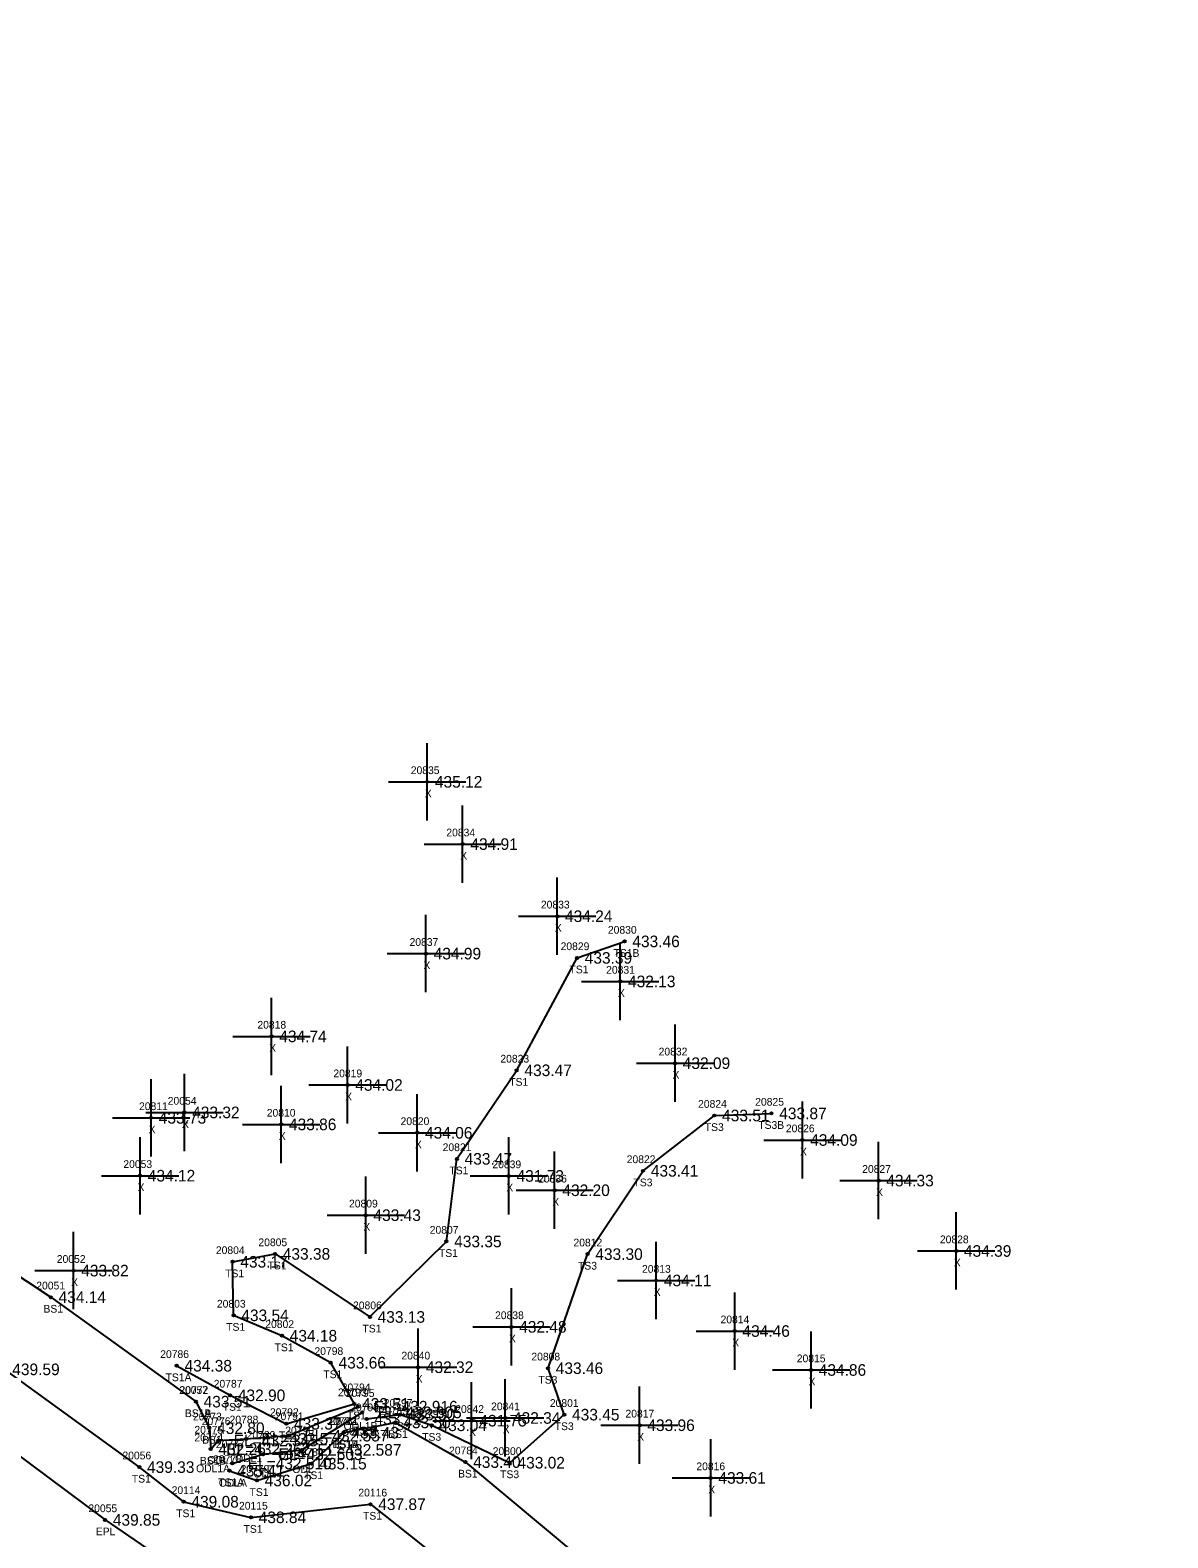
# Model space of a CAD drawing. Extents: x 1613836 to 1615109, y 777151 to 778248.
# Drawn here: x 1614182.4 to 1614329.5, y 777918.3 to 778113.4 of the extents above; entities that cross this region are included whole.
import ezdxf

# ---------------------------------------------------------------- set-up
doc = ezdxf.new("R2010")
doc.units = 0
for name, color, linetype in [('RD_DTM_BkLn2', 7, 'Continuous'), ('RD_DTM_BkLn_txCode', 7, 'Continuous'), ('RD_EX_H2O', 7, 'Continuous'), ('RD_EX_H2O_txCode', 7, 'Continuous'), ('RD_EX_Misc', 7, 'Continuous'), ('RD_EX_Misc_txCode', 7, 'Continuous'), ('RD_EX_Road', 7, 'Continuous'), ('RD_EX_Road_txCode', 7, 'Continuous'), ('RD_EX_TX_H2O_ELEV', 7, 'Continuous'), ('RD_EX_TX_Misc_ELEV', 7, 'Continuous'), ('RD_EX_TX_Road_ELEV', 7, 'Continuous'), ('RD_SMD_Locator', 7, 'Continuous')]:
    doc.layers.add(name, color=color, linetype=linetype)

msp = doc.modelspace()

# ---------------------------------------------------------------- linework, layer by layer
at = {"layer": 'RD_DTM_BkLn2'}
for points in [[(1613872.63, 778113.36), (1613919.46, 778094.34), (1613965.43, 778074.52), (1614011.49, 778053.16), (1614057.96, 778027.92), (1614098.58, 778001.66), (1614142.66, 777977.46), (1614185.05, 777949.4), (1614203.81, 777935.88)], [(1613870.65, 778107.91), (1613917.36, 778089.81), (1613963.47, 778068.53), (1614008.76, 778046.32), (1614052.42, 778023.01), (1614094.96, 777996.37), (1614137.71, 777969), (1614179.06, 777940.06), (1614196.49, 777927.41), (1614202.23, 777922.93), (1614210.94, 777920.91), (1614226.4, 777922.61), (1614267.62, 777889.85), (1614307.16, 777859.76), (1614381.32, 777790.21), (1614451.43, 777721.4), (1614453.49, 777722.08), (1614455.33, 777720.48), (1614437.07, 777696.16)], [(1614201.34, 777940.53), (1614208.24, 777936.7), (1614215.51, 777933.02), (1614224.31, 777935.59), (1614221.26, 777940.92), (1614214.95, 777944.41), (1614208.69, 777947.05), (1614208.56, 777953.98), (1614214.05, 777955), (1614226.32, 777946.84), (1614236.22, 777956.61), (1614237.57, 777967.3), (1614245.31, 777978.76), (1614253.11, 777993.31), (1614259.27, 777995.44)], [(1614225.91, 777933.64), (1614230.23, 777934.21), (1614234.33, 777932.82), (1614244.41, 777927.98), (1614251.47, 777934.2), (1614249.36, 777940.21), (1614254.48, 777954.97), (1614261.66, 777965.75), (1614270.88, 777972.91), (1614278.27, 777973.18)], [(1614203.81, 777935.88), (1614205.56, 777932.45), (1614205.73, 777929.74)], [(1614208.15, 777926.94), (1614211.71, 777925.68), (1614218.77, 777927.86), (1614222.94, 777931.87)], [(1614222.94, 777931.87), (1614229.64, 777933.19), (1614238.68, 777928.06), (1614263.24, 777907.54)]]:
    msp.add_lwpolyline(points, dxfattribs=at)
at = {"layer": 'RD_EX_H2O'}
for points in [[(1614205.73, 777929.74), (1614206.71, 777930.85), (1614210.29, 777931.06), (1614215.85, 777931.48), (1614224.8, 777935.23)], [(1614208.51, 777927.88), (1614212.5, 777929.07), (1614217.53, 777929.64), (1614225.32, 777934.49)]]:
    msp.add_lwpolyline(points, dxfattribs=at)
at = {"layer": 'RD_EX_Misc'}
for p, q in [((1614233.73, 778011.09), (1614233.73, 778021.09)), ((1614228.73, 778016.09), (1614238.73, 778016.09)), ((1614238.32, 778003.03), (1614238.32, 778013.03)), ((1614233.32, 778008.03), (1614243.32, 778008.03)), ((1614250.56, 777993.7), (1614250.56, 778003.7)), ((1614233.57, 777988.86), (1614233.57, 777998.86)), ((1614245.56, 777998.7), (1614255.56, 777998.7)), ((1614258.71, 777985.26), (1614258.71, 777995.26)), ((1614228.57, 777993.86), (1614238.57, 777993.86)), ((1614253.71, 777990.26), (1614263.71, 777990.26)), ((1614213.6, 777978.15), (1614213.6, 777988.15)), ((1614265.79, 777974.68), (1614265.79, 777984.68)), ((1614208.6, 777983.15), (1614218.6, 777983.15)), ((1614223.43, 777971.86), (1614223.43, 777981.86)), ((1614260.79, 777979.68), (1614270.79, 777979.68)), ((1614198.01, 777967.61), (1614198.01, 777977.61)), ((1614202.33, 777968.31), (1614202.33, 777978.31)), ((1614214.85, 777966.76), (1614214.85, 777976.76)), ((1614218.43, 777976.86), (1614228.43, 777976.86)), ((1614232.45, 777965.67), (1614232.45, 777975.67)), ((1614282.27, 777964.74), (1614282.27, 777974.74)), ((1614197.33, 777973.31), (1614207.33, 777973.31)), ((1614193.01, 777972.61), (1614203.01, 777972.61)), ((1614209.85, 777971.76), (1614219.85, 777971.76)), ((1614196.59, 777960.12), (1614196.59, 777970.12)), ((1614227.45, 777970.67), (1614237.45, 777970.67)), ((1614244.29, 777960.09), (1614244.29, 777970.09)), ((1614277.27, 777969.74), (1614287.27, 777969.74)), ((1614292.12, 777959.49), (1614292.12, 777969.49)), ((1614250.22, 777958.24), (1614250.22, 777968.24)), ((1614191.59, 777965.12), (1614201.59, 777965.12)), ((1614225.78, 777955.01), (1614225.78, 777965.01)), ((1614239.29, 777965.09), (1614249.29, 777965.09)), ((1614245.22, 777963.24), (1614255.22, 777963.24)), ((1614287.12, 777964.49), (1614297.12, 777964.49)), ((1614220.78, 777960.01), (1614230.78, 777960.01)), ((1614302.16, 777950.38), (1614302.16, 777960.38)), ((1614187.98, 777947.84), (1614187.98, 777957.84)), ((1614263.35, 777946.56), (1614263.35, 777956.56)), ((1614297.16, 777955.38), (1614307.16, 777955.38)), ((1614182.98, 777952.84), (1614192.98, 777952.84)), ((1614258.35, 777951.56), (1614268.35, 777951.56)), ((1614244.63, 777940.56), (1614244.63, 777950.56)), ((1614273.51, 777940.02), (1614273.51, 777950.02)), ((1614239.63, 777945.56), (1614249.63, 777945.56)), ((1614232.56, 777935.34), (1614232.56, 777945.34)), ((1614268.51, 777945.02), (1614278.51, 777945.02)), ((1614283.38, 777934.98), (1614283.38, 777944.98)), ((1614227.56, 777940.34), (1614237.56, 777940.34)), ((1614278.38, 777939.98), (1614288.38, 777939.98)), ((1614239.48, 777928.42), (1614239.48, 777938.42)), ((1614243.83, 777928.77), (1614243.83, 777938.77)), ((1614261.21, 777927.83), (1614261.21, 777937.83)), ((1614238.83, 777933.77), (1614248.83, 777933.77)), ((1614234.48, 777933.42), (1614244.48, 777933.42)), ((1614256.21, 777932.83), (1614266.21, 777932.83)), ((1614270.4, 777921.01), (1614270.4, 777931.01)), ((1614265.4, 777926.01), (1614275.4, 777926.01))]:
    msp.add_line(p, q, dxfattribs=at)
at = {"layer": 'RD_EX_Road'}
msp.add_lwpolyline([(1613868.87, 778104.15), (1613915.02, 778083.82), (1613960.16, 778062.2), (1614004.58, 778040.28), (1614048.84, 778015.98), (1614091.38, 777990.08), (1614134.36, 777962.6), (1614174.73, 777933.48), (1614192.07, 777920.58), (1614215.93, 777904.23), (1614254.59, 777873.05), (1614293.82, 777842.42), (1614371.74, 777779.59), (1614449.33, 777716.3), (1614443.98, 777709.72), (1614439.38, 777704.09)], dxfattribs=at)
at = {"layer": 'RD_SMD_Locator'}
for centre in [(1614233.73, 778016.09), (1614238.32, 778008.03), (1614250.56, 777998.7), (1614259.27, 777995.44), (1614233.57, 777993.86), (1614253.11, 777993.31), (1614258.71, 777990.26), (1614213.6, 777983.15), (1614245.31, 777978.76), (1614265.79, 777979.68), (1614223.43, 777976.86), (1614198.01, 777972.61), (1614202.33, 777973.31), (1614270.88, 777972.91), (1614278.27, 777973.18), (1614214.85, 777971.76), (1614232.45, 777970.67), (1614282.27, 777969.74), (1614237.57, 777967.3), (1614196.59, 777965.12), (1614244.29, 777965.09), (1614261.66, 777965.75), (1614250.22, 777963.24), (1614292.12, 777964.49), (1614225.78, 777960.01), (1614214.05, 777955), (1614236.22, 777956.61), (1614254.48, 777954.97), (1614302.16, 777955.38), (1614208.56, 777953.98), (1614187.98, 777952.84), (1614263.35, 777951.56), (1614185.05, 777949.4), (1614208.69, 777947.05), (1614226.32, 777946.84), (1614244.63, 777945.56), (1614214.95, 777944.41), (1614273.51, 777945.02), (1614201.34, 777940.53), (1614221.26, 777940.92), (1614232.56, 777940.34), (1614249.36, 777940.21), (1614283.38, 777939.98), (1614203.81, 777935.88), (1614203.81, 777935.88), (1614208.24, 777936.7), (1614224.31, 777935.59), (1614224.8, 777935.23), (1614225.32, 777934.49), (1614225.91, 777933.64), (1614230.23, 777934.21), (1614243.83, 777933.77), (1614251.47, 777934.2), (1614205.56, 777932.45), (1614215.51, 777933.02), (1614222.94, 777931.87), (1614222.94, 777931.87), (1614229.64, 777933.19), (1614234.33, 777932.82), (1614239.48, 777933.42), (1614261.21, 777932.83), (1614205.73, 777929.74), (1614205.73, 777929.74), (1614206.71, 777930.85), (1614210.29, 777931.06), (1614215.85, 777931.48), (1614217.53, 777929.64), (1614208.51, 777927.88), (1614212.5, 777929.07), (1614218.77, 777927.86), (1614238.68, 777928.06), (1614244.41, 777927.98), (1614196.49, 777927.41), (1614208.15, 777926.94), (1614270.4, 777926.01), (1614211.71, 777925.68), (1614202.23, 777922.93), (1614226.4, 777922.61), (1614192.07, 777920.58), (1614210.94, 777920.91)]:
    msp.add_circle(centre, 0.15, dxfattribs=at)

# ---------------------------------------------------------------- texts
at = {"layer": 'RD_DTM_BkLn_txCode'}
for s, p in [('20830', (1614257.11, 777996.44)), ('20829', (1614250.99, 777994.31)), ('TS1B', (1614257.84, 777993.44)), ('TS1', (1614252.14, 777991.31)), ('20823', (1614243.2, 777979.76)), ('TS1', (1614244.35, 777976.76)), ('20824', (1614268.77, 777973.91)), ('20825', (1614276.16, 777974.18)), ('TS3', (1614269.64, 777970.91)), ('TS3B', (1614276.56, 777971.18)), ('20821', (1614235.73, 777968.3)), ('20822', (1614259.54, 777966.75)), ('TS1', (1614236.61, 777965.3)), ('TS3', (1614260.42, 777963.75)), ('20807', (1614234.06, 777957.61)), ('20804', (1614206.4, 777954.98)), ('20805', (1614211.9, 777956)), ('TS1', (1614235.26, 777954.61)), ('20812', (1614252.65, 777955.97)), ('TS1', (1614213.09, 777953)), ('TS3', (1614253.24, 777952.97)), ('20051', (1614183.17, 777950.4)), ('TS1', (1614207.6, 777951.98)), ('BS1', (1614184.1, 777947.4)), ('20803', (1614206.53, 777948.05)), ('20806', (1614224.14, 777947.84)), ('TS1', (1614207.73, 777945.05)), ('20802', (1614212.79, 777945.41)), ('TS1', (1614225.36, 777944.84)), ('TS1', (1614213.99, 777942.41)), ('20786', (1614199.2, 777941.53)), ('20798', (1614219.15, 777941.92)), ('20808', (1614247.21, 777941.21)), ('TS1A', (1614199.89, 777938.53)), ('TS1', (1614220.3, 777938.92)), ('20057', (1614201.66, 777936.88)), ('20772', (1614201.7, 777936.88)), ('20787', (1614206.12, 777937.7)), ('20793', (1614222.19, 777936.59)), ('TS3', (1614248.12, 777938.21)), ('TS1', (1614207.28, 777934.7)), ('20796', (1614223.77, 777934.64)), ('20797', (1614228.11, 777935.21)), ('20801', (1614249.6, 777935.2)), ('BS1A', (1614202.38, 777933.88)), ('BS1B', (1614202.4, 777933.88)), ('20773', (1614203.44, 777933.45)), ('20792', (1614213.39, 777934.02)), ('20782', (1614220.82, 777932.87)), ('20781', (1614221.1, 777932.87)), ('TS1', (1614223.35, 777933.59)), ('20783', (1614227.52, 777934.19)), ('20799', (1614232.22, 777933.82)), ('20774', (1614203.62, 777930.74)), ('TS1', (1614214.55, 777931.02)), ('TS3A', (1614224.18, 777931.64)), ('BS1', (1614228.69, 777931.19)), ('TS3', (1614228.99, 777932.21)), ('TS3', (1614233.09, 777930.82)), ('TS3', (1614250.23, 777932.2)), ('BS1', (1614204.62, 777930.45)), ('20780', (1614216.62, 777928.86)), ('TS1B', (1614221.5, 777929.87)), ('BS1A', (1614221.5, 777929.87)), ('20784', (1614236.56, 777929.06)), ('20800', (1614242.21, 777928.98)), ('20056', (1614194.31, 777928.41)), ('BS1B', (1614204.32, 777927.74)), ('20778', (1614206.03, 777927.94)), ('TS1', (1614195.53, 777925.41)), ('TS1A', (1614206.7, 777924.94)), ('20779', (1614209.59, 777926.68)), ('TS1', (1614217.81, 777925.86)), ('BS1', (1614237.73, 777926.06)), ('TS3', (1614243.17, 777925.98)), ('20114', (1614200.68, 777923.93)), ('TS1', (1614210.75, 777923.68)), ('20116', (1614224.83, 777923.61)), ('TS1', (1614201.27, 777920.93)), ('20115', (1614209.39, 777921.91)), ('TS1', (1614225.44, 777920.61)), ('TS1', (1614209.98, 777918.91))]:
    msp.add_text(s, height=1, dxfattribs=at).set_placement(p)
at = {"layer": 'RD_EX_H2O_txCode'}
for s, p in [('20794', (1614222.68, 777937.23)), ('20795', (1614223.2, 777936.49)), ('20776', (1614204.57, 777932.85)), ('20788', (1614208.17, 777933.06)), ('20791', (1614214.02, 777933.48)), ('20775', (1614203.62, 777931.74)), ('20789', (1614210.38, 777931.07)), ('20790', (1614215.37, 777931.64)), ('ODL1B', (1614222.92, 777932.23)), ('ODLB', (1614223.6, 777931.49)), ('20777', (1614206.4, 777929.88)), ('ODL1', (1614205.3, 777927.85)), ('ODL1', (1614208.88, 777928.06)), ('ODL1', (1614214.44, 777928.48)), ('ODL1A', (1614203.84, 777926.74)), ('ODLA', (1614206.78, 777924.88)), ('ODL', (1614211.26, 777926.07)), ('ODL', (1614216.29, 777926.64))]:
    msp.add_text(s, height=1, dxfattribs=at).set_placement(p)
at = {"layer": 'RD_EX_Misc_txCode'}
for s, p in [('20835', (1614231.61, 778017.09)), ('X', (1614233.42, 778014.09)), ('20834', (1614236.21, 778009.03)), ('X', (1614238.01, 778006.03)), ('20833', (1614248.44, 777999.7)), ('X', (1614250.24, 777996.7)), ('20837', (1614231.45, 777994.86)), ('X', (1614233.25, 777991.86)), ('20831', (1614256.88, 777991.26)), ('X', (1614258.4, 777988.26)), ('20818', (1614211.77, 777984.15)), ('X', (1614213.29, 777981.15)), ('20832', (1614263.67, 777980.68)), ('20819', (1614221.6, 777977.86)), ('X', (1614265.47, 777977.68)), ('20811', (1614196.46, 777973.61)), ('20054', (1614200.17, 777974.31)), ('X', (1614223.12, 777974.86)), ('20810', (1614212.98, 777972.76)), ('20820', (1614230.29, 777971.67)), ('X', (1614197.7, 777970.61)), ('X', (1614202.01, 777971.31)), ('X', (1614214.54, 777969.76)), ('20826', (1614280.13, 777970.74)), ('X', (1614232.14, 777968.67)), ('20053', (1614194.43, 777966.12)), ('20839', (1614242.17, 777966.09)), ('X', (1614281.96, 777967.74)), ('20836', (1614248.08, 777964.24)), ('20827', (1614290, 777965.49)), ('X', (1614196.27, 777963.12)), ('X', (1614243.97, 777963.09)), ('X', (1614291.8, 777962.49)), ('20809', (1614223.62, 777961.01)), ('X', (1614249.91, 777961.24)), ('X', (1614225.47, 777958.01)), ('20828', (1614300.05, 777956.38)), ('20052', (1614185.82, 777953.84)), ('20813', (1614261.52, 777952.56)), ('X', (1614301.85, 777953.38)), ('X', (1614187.67, 777950.84)), ('X', (1614263.04, 777949.56)), ('20838', (1614242.51, 777946.56)), ('20814', (1614271.68, 777946.02)), ('X', (1614244.31, 777943.56)), ('X', (1614273.2, 777943.02)), ('20840', (1614230.4, 777941.34)), ('20815', (1614281.54, 777940.98)), ('X', (1614232.25, 777938.34)), ('X', (1614283.06, 777937.98)), ('20841', (1614242, 777934.77)), ('20842', (1614237.36, 777934.42)), ('20817', (1614259.38, 777933.83)), ('X', (1614239.16, 777931.42)), ('X', (1614243.52, 777931.77)), ('X', (1614260.9, 777930.83)), ('20816', (1614268.55, 777927.01)), ('X', (1614270.09, 777924.01))]:
    msp.add_text(s, height=1, dxfattribs=at).set_placement(p)
at = {"layer": 'RD_EX_Road_txCode'}
for s, p in [('20055', (1614189.91, 777921.58)), ('EPL', (1614190.87, 777918.58))]:
    msp.add_text(s, height=1, dxfattribs=at).set_placement(p)
at = {"layer": 'RD_EX_TX_H2O_ELEV'}
for s, p in [('EL=432.916', (1614226.8, 777934.48)), ('EL=432.805', (1614227.32, 777933.74)), ('EL=432.572', (1614212.29, 777930.31)), ('EL=432.557', (1614217.85, 777930.73)), ('EL=432.262', (1614207.73, 777928.99)), ('EL=432.345', (1614208.71, 777930.1)), ('EL=432.603', (1614214.5, 777928.32)), ('EL=432.587', (1614219.53, 777928.89)), ('EL=432.510', (1614210.51, 777927.13))]:
    msp.add_text(s, height=1.5, dxfattribs=at).set_placement(p)
at = {"layer": 'RD_EX_TX_Misc_ELEV'}
for s, p in [('435.12', (1614234.73, 778015.34)), ('434.91', (1614239.32, 778007.28)), ('434.24', (1614251.56, 777997.95)), ('433.46', (1614260.27, 777994.69)), ('434.99', (1614234.57, 777993.11)), ('433.39', (1614254.11, 777992.56)), ('432.13', (1614259.71, 777989.51)), ('434.74', (1614214.6, 777982.4)), ('433.47', (1614246.31, 777978.01)), ('432.09', (1614266.79, 777978.93)), ('434.02', (1614224.43, 777976.11)), ('433.73', (1614199.01, 777971.86)), ('433.32', (1614203.33, 777972.56)), ('433.51', (1614271.88, 777972.16)), ('433.87', (1614279.27, 777972.43)), ('433.86', (1614215.85, 777971.01)), ('434.06', (1614233.45, 777969.92)), ('434.09', (1614283.27, 777968.99)), ('433.47', (1614238.57, 777966.55)), ('434.12', (1614197.59, 777964.37)), ('431.73', (1614245.29, 777964.34)), ('433.41', (1614262.66, 777965)), ('434.33', (1614293.12, 777963.74)), ('432.20', (1614251.22, 777962.49)), ('433.43', (1614226.78, 777959.26)), ('433.35', (1614237.22, 777955.86)), ('433.38', (1614215.05, 777954.25)), ('433.30', (1614255.48, 777954.22)), ('434.39', (1614303.16, 777954.63)), ('433.82', (1614188.98, 777952.09)), ('433.17', (1614209.56, 777953.23)), ('434.11', (1614264.35, 777950.81)), ('434.14', (1614186.05, 777948.65)), ('433.54', (1614209.69, 777946.3)), ('433.13', (1614227.32, 777946.09)), ('432.48', (1614245.63, 777944.81)), ('434.46', (1614274.51, 777944.27)), ('434.18', (1614215.95, 777943.66)), ('433.66', (1614222.26, 777940.17)), ('439.59', (1614180.06, 777939.31)), ('434.38', (1614202.34, 777939.78)), ('432.32', (1614233.56, 777939.59)), ('433.46', (1614250.36, 777939.46)), ('434.86', (1614284.38, 777939.23)), ('433.51', (1614204.81, 777935.13)), ('433.51', (1614204.81, 777935.13)), ('432.90', (1614209.24, 777935.95)), ('433.51', (1614225.31, 777934.84)), ('433.37', (1614216.51, 777932.27)), ('433.12', (1614226.91, 777932.89)), ('433.50', (1614230.64, 777932.44)), ('433.30', (1614231.23, 777933.46)), ('431.75', (1614240.48, 777932.67)), ('432.34', (1614244.83, 777933.02)), ('433.45', (1614252.47, 777933.45)), ('432.80', (1614206.56, 777931.7)), ('433.43', (1614223.94, 777931.12)), ('433.43', (1614223.94, 777931.12)), ('433.04', (1614235.33, 777932.07)), ('433.96', (1614262.21, 777932.08)), ('432.26', (1614206.73, 777928.99)), ('439.33', (1614197.49, 777926.66)), ('435.15', (1614219.77, 777927.11)), ('433.40', (1614239.68, 777927.31)), ('433.02', (1614245.41, 777927.23)), ('435.41', (1614209.15, 777926.19)), ('436.02', (1614212.71, 777924.93)), ('433.61', (1614271.4, 777925.26)), ('439.08', (1614203.23, 777922.18)), ('437.87', (1614227.4, 777921.86)), ('438.84', (1614211.94, 777920.16))]:
    msp.add_text(s, height=1.5, dxfattribs=at).set_placement(p)
at = {"layer": 'RD_EX_TX_Road_ELEV'}
msp.add_text('439.85', height=1.5, dxfattribs=at).set_placement((1614193.07, 777919.83))

doc.saveas('drawing.dxf')
